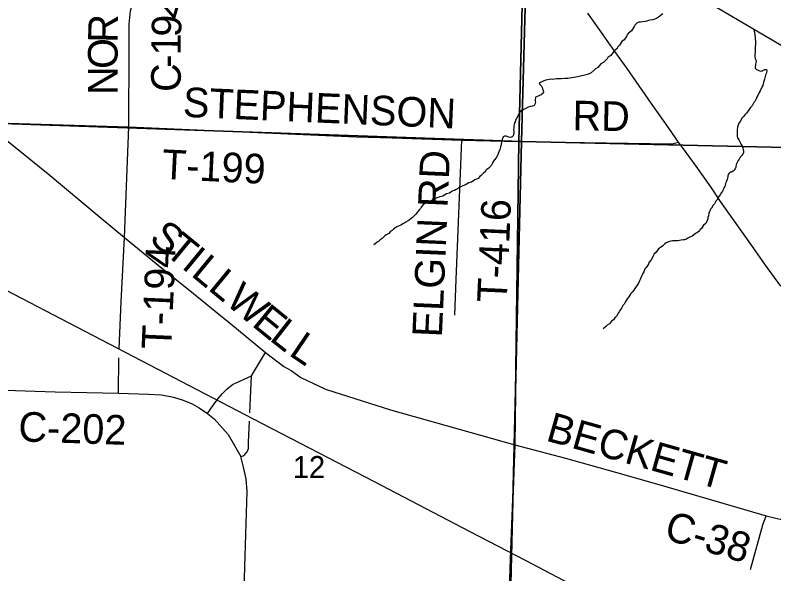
# Model space of a CAD drawing. Extents: x 0 to 34, y 0 to 22.
# Drawn here: x 4.391 to 5.846, y 15.693 to 16.765 of the extents above; entities that cross this region are included whole.
import ezdxf

# ---------------------------------------------------------------- set-up
doc = ezdxf.new("R2010")
doc.units = 0
for name, color, linetype in [('Default', 7, 'Continuous'), ('GM_X_County_Road', 7, 'Continuous'), ('GM_X_County_Road_Text', 7, 'Continuous'), ('GM_X_Minor_River', 7, 'Continuous'), ('GM_X_Rail_Line', 7, 'Continuous'), ('GM_X_Section', 7, 'Continuous'), ('GM_X_Section_Text', 7, 'Continuous'), ('GM_X_Township_Road', 7, 'Continuous'), ('GM_X_Township_Road_Text', 7, 'Continuous'), ('GM_X_US_Route', 7, 'Continuous'), ('SH_Text', 7, 'Continuous')]:
    doc.layers.add(name, color=color, linetype=linetype)

msp = doc.modelspace()

# ---------------------------------------------------------------- linework, layer by layer
at = {"layer": 'Default'}
for points in [[(5.3679, 16.9967), (5.3666, 16.941), (5.3568, 16.5234), (5.3489, 15.9414), (5.3456, 15.8536), (5.3407, 15.722), (5.3386, 15.6646)], [(5.3386, 15.6646), (5.3407, 15.722), (5.3456, 15.8536), (5.3489, 15.9414), (5.3568, 16.5234), (5.3666, 16.941), (5.3679, 16.9967)]]:
    msp.add_lwpolyline(points, dxfattribs=at)
at = {"layer": 'GM_X_County_Road'}
for points in [[(4.6008, 16.339), (4.609, 16.551), (4.6097, 16.6991), (4.6094, 16.7478), (4.6122, 16.7735), (4.6186, 16.7955), (4.6308, 16.8329), (4.6404, 16.8545), (4.6484, 16.8669), (4.6536, 16.8737), (4.6626, 16.8795), (4.6788, 16.8827), (4.6826, 16.8976), (4.6855, 16.9599), (4.6881, 17.0461), (4.7038, 17.5502)], [(2.8366, 17.427), (2.8842, 17.4004), (2.9456, 17.3674), (3.0402, 17.3171), (3.14, 17.2646), (3.2189, 17.2229), (3.3942, 17.1285), (3.5659, 17.0329), (3.7657, 16.9226), (3.8318, 16.8854), (3.9996, 16.7931), (4.1007, 16.7381), (4.138, 16.7114), (4.1787, 16.6782), (4.3308, 16.5597), (4.3911, 16.5119), (4.4541, 16.461), (4.552, 16.3788), (4.6008, 16.339), (4.6722, 16.2801), (4.7258, 16.2367), (4.7883, 16.1861)], [(4.7883, 16.1861), (4.8004, 16.1763), (4.8711, 16.1183), (4.9063, 16.0915), (4.9201, 16.0832), (4.9384, 16.0698), (4.9847, 16.0482)], [(4.7598, 16.001), (4.7713, 16.0175), (4.7803, 16.0295), (4.7887, 16.0392), (4.7964, 16.0478), (4.8077, 16.0567), (4.844, 16.0731), (4.8711, 16.1183)], [(4.3333, 16.047), (4.4673, 16.0429), (4.5889, 16.0401)], [(4.9847, 16.0482), (4.9875, 16.0469), (5.1107, 16.0081), (5.3492, 15.9409)], [(4.5889, 16.0401), (4.6466, 16.0383), (4.6717, 16.0367), (4.6942, 16.0323), (4.7129, 16.0263), (4.7301, 16.0196), (4.7434, 16.012), (4.7598, 16.001)], [(5.3492, 15.9409), (5.4463, 15.9156), (5.558, 15.8841), (5.6405, 15.8603), (5.7937, 15.8156), (5.8306, 15.8045), (5.9105, 15.7856), (5.9646, 15.7778), (6.0771, 15.7639), (6.1234, 15.7574)]]:
    msp.add_lwpolyline(points, dxfattribs=at)
at = {"layer": 'GM_X_Minor_River'}
for points in [[(5.6328, 16.7675), (5.6247, 16.7612), (5.6208, 16.7591), (5.6135, 16.7566), (5.6086, 16.7556), (5.6055, 16.7549), (5.6021, 16.7538), (5.599, 16.7528), (5.5944, 16.7525), (5.5899, 16.7519), (5.5868, 16.7516), (5.583, 16.7501), (5.5787, 16.7461), (5.5779, 16.7438), (5.5724, 16.7352), (5.5666, 16.7308), (5.5638, 16.7271), (5.563, 16.7244), (5.5583, 16.7181), (5.5544, 16.7147), (5.5497, 16.7076), (5.5458, 16.7039), (5.545, 16.7013), (5.5411, 16.698), (5.5387, 16.6958), (5.5328, 16.6876), (5.5271, 16.6839), (5.5262, 16.6816), (5.5196, 16.675), (5.5138, 16.6717), (5.508, 16.665), (5.5037, 16.6624), (5.501, 16.6599), (5.4952, 16.6547), (5.4929, 16.6532), (5.4883, 16.6514), (5.4833, 16.6504), (5.4749, 16.6483), (5.4661, 16.6463), (5.4585, 16.6453), (5.4505, 16.644), (5.4447, 16.6438), (5.4383, 16.6432), (5.4333, 16.6433), (5.4288, 16.643), (5.4249, 16.6424), (5.4211, 16.6421), (5.4181, 16.6422), (5.4146, 16.6415), (5.4082, 16.6405), (5.4047, 16.6391), (5.3997, 16.6365), (5.3959, 16.6355), (5.3969, 16.6324), (5.3999, 16.6289), (5.4014, 16.6266)], [(5.8074, 16.738), (5.8088, 16.7283), (5.8104, 16.7138), (5.8093, 16.6849)], [(5.8093, 16.6849), (5.81, 16.6818), (5.811, 16.6795), (5.8114, 16.6765), (5.8105, 16.6712), (5.8104, 16.6685), (5.81, 16.6659), (5.8099, 16.6636), (5.8125, 16.6609), (5.8167, 16.6589), (5.8197, 16.6576), (5.8231, 16.6587), (5.8254, 16.6598), (5.8281, 16.6608), (5.8312, 16.6612), (5.8318, 16.6577), (5.8306, 16.6528), (5.8298, 16.6502), (5.8277, 16.6422), (5.8265, 16.6389), (5.826, 16.6366), (5.8244, 16.6306), (5.8224, 16.6272), (5.8196, 16.62), (5.8172, 16.6167), (5.8144, 16.6099), (5.812, 16.6069), (5.8116, 16.6047), (5.8088, 16.5998), (5.8069, 16.5976), (5.8057, 16.5949), (5.8037, 16.5912), (5.8009, 16.5882), (5.7962, 16.5819), (5.7939, 16.5777), (5.7904, 16.5748), (5.7876, 16.5707), (5.7845, 16.5681), (5.7809, 16.561), (5.7786, 16.558), (5.7757, 16.5501), (5.7752, 16.5452), (5.7755, 16.5425), (5.7754, 16.5383), (5.775, 16.5353), (5.7753, 16.533), (5.776, 16.5299), (5.7786, 16.5261), (5.7815, 16.5199), (5.7829, 16.5172), (5.7848, 16.5145), (5.7862, 16.5099), (5.7869, 16.5073), (5.7876, 16.5042), (5.7875, 16.5015), (5.7863, 16.4985), (5.784, 16.4959), (5.7812, 16.493), (5.7792, 16.4888), (5.7773, 16.4862), (5.7749, 16.4813), (5.7733, 16.4787), (5.7724, 16.4734), (5.7716, 16.4704), (5.7696, 16.4678), (5.7673, 16.466), (5.7642, 16.4641), (5.7619, 16.4638), (5.7596, 16.462), (5.758, 16.4597), (5.7564, 16.4526), (5.7559, 16.4499), (5.7547, 16.4465), (5.7535, 16.4443), (5.7514, 16.4367), (5.7495, 16.4337), (5.749, 16.4315), (5.747, 16.4273), (5.7451, 16.4251), (5.7427, 16.4206), (5.74, 16.4176), (5.736, 16.4105), (5.7344, 16.4083), (5.732, 16.403), (5.7293, 16.4008), (5.7261, 16.3952), (5.7242, 16.393), (5.7222, 16.3881), (5.721, 16.3858), (5.7201, 16.3801), (5.7192, 16.3771), (5.7188, 16.3745), (5.718, 16.3715), (5.7152, 16.3658), (5.7109, 16.3621), (5.707, 16.3562), (5.7043, 16.3543), (5.7027, 16.3517), (5.6992, 16.348), (5.6953, 16.3466), (5.6918, 16.3429)], [(5.4014, 16.6266), (5.4021, 16.6239), (5.4035, 16.6205), (5.4038, 16.6178), (5.403, 16.6156), (5.3991, 16.6126), (5.3964, 16.6112), (5.3938, 16.6101), (5.3915, 16.609), (5.3888, 16.6076), (5.3879, 16.6027), (5.3878, 16.5996), (5.3885, 16.5973), (5.3873, 16.5943), (5.3857, 16.5921), (5.3827, 16.5906), (5.3792, 16.5899), (5.3742, 16.5886), (5.3677, 16.5849), (5.3635, 16.5835), (5.3596, 16.5813), (5.358, 16.5787), (5.3557, 16.5738), (5.3513, 16.566), (5.3501, 16.5637), (5.3493, 16.5607), (5.3484, 16.5584), (5.3476, 16.5554), (5.3472, 16.5531), (5.3467, 16.5482), (5.3466, 16.5459), (5.347, 16.5436), (5.3469, 16.5391), (5.3464, 16.5368), (5.3456, 16.5338), (5.344, 16.5316), (5.3398, 16.5305), (5.3372, 16.5314), (5.3326, 16.533), (5.3288, 16.5331), (5.3265, 16.532), (5.3245, 16.5264), (5.3241, 16.5237), (5.3232, 16.5211), (5.3223, 16.5146), (5.3215, 16.5124), (5.3203, 16.5078), (5.3183, 16.5033), (5.3167, 16.4996), (5.3162, 16.4973), (5.3134, 16.4913), (5.3095, 16.4872), (5.3068, 16.4835), (5.3056, 16.4801), (5.304, 16.4775), (5.2993, 16.4719), (5.2935, 16.4679), (5.2927, 16.4652), (5.2888, 16.4623), (5.2845, 16.4578), (5.2818, 16.4556), (5.2787, 16.4519), (5.2725, 16.4494), (5.2656, 16.4446), (5.2606, 16.4436), (5.2544, 16.4396), (5.2494, 16.4378), (5.2429, 16.4349), (5.239, 16.432), (5.2367, 16.4305), (5.2333, 16.4291), (5.229, 16.4273), (5.2236, 16.424), (5.2179, 16.4223), (5.2106, 16.4183), (5.2048, 16.4169), (5.201, 16.4155), (5.1964, 16.4133), (5.1933, 16.4122), (5.1891, 16.4089), (5.1841, 16.4075), (5.1775, 16.4039), (5.1737, 16.4025), (5.1718, 16.4002), (5.1694, 16.3969), (5.1682, 16.3942), (5.1659, 16.3924), (5.1635, 16.389), (5.1615, 16.3864), (5.1588, 16.3835), (5.1553, 16.3794), (5.1526, 16.3772), (5.1502, 16.3749), (5.1464, 16.372), (5.1441, 16.3709), (5.1402, 16.368), (5.1379, 16.3669), (5.1356, 16.3654), (5.1302, 16.3625), (5.1271, 16.3611), (5.1229, 16.3589)], [(5.1229, 16.3589), (5.1186, 16.3564), (5.1163, 16.3545), (5.1136, 16.3519), (5.1101, 16.3493), (5.1074, 16.3464), (5.1047, 16.3453), (5.1024, 16.3438), (5.0997, 16.3416), (5.0966, 16.339), (5.0946, 16.3368), (5.0907, 16.3339), (5.0872, 16.3313), (5.0849, 16.3298), (5.0811, 16.3265), (5.0783, 16.3243)], [(5.6918, 16.3429), (5.6887, 16.3414), (5.6857, 16.34), (5.683, 16.3385), (5.6807, 16.3371), (5.6783, 16.3352), (5.6745, 16.3342), (5.6715, 16.3339), (5.6677, 16.3336), (5.6612, 16.3322), (5.657, 16.3323), (5.6543, 16.332), (5.6513, 16.3321), (5.6478, 16.3318), (5.6436, 16.3304), (5.639, 16.3282), (5.6363, 16.3264), (5.6328, 16.3227), (5.6285, 16.3197), (5.6243, 16.3172), (5.6192, 16.3101), (5.6153, 16.3068), (5.6145, 16.3041), (5.6101, 16.2959), (5.6058, 16.291), (5.605, 16.2876), (5.6006, 16.2809), (5.5983, 16.2783), (5.5963, 16.2727), (5.5943, 16.2693), (5.5927, 16.2655), (5.5907, 16.261), (5.5895, 16.2584), (5.5879, 16.2558), (5.5859, 16.2513), (5.5819, 16.2453), (5.5788, 16.2408), (5.5768, 16.2374), (5.5741, 16.2337), (5.5713, 16.2311), (5.5674, 16.2248), (5.5646, 16.221), (5.5627, 16.2177), (5.5607, 16.2147), (5.5583, 16.2109), (5.556, 16.2083), (5.5536, 16.2034), (5.5516, 16.2008), (5.5492, 16.196), (5.5469, 16.1934), (5.5437, 16.1874), (5.5406, 16.1848), (5.5379, 16.181), (5.534, 16.1781), (5.5304, 16.1729), (5.5262, 16.1703), (5.5227, 16.167), (5.5181, 16.1633)]]:
    msp.add_lwpolyline(points, dxfattribs=at)
at = {"layer": 'GM_X_Rail_Line'}
msp.add_lwpolyline([(4.034, 16.414), (4.8469, 15.9911), (5.0791, 15.8704), (5.2629, 15.7745), (5.3698, 15.7189), (5.5376, 15.6307)], dxfattribs=at)
at = {"layer": 'GM_X_Section'}
for points in [[(4.38, 17.558), (5.3894, 17.5316), (5.3619, 16.5226), (4.3467, 16.5583)], [(5.3894, 17.5316), (6.392, 17.5084), (6.4295, 17.5071), (6.4046, 16.4989), (5.3619, 16.5226)], [(4.3467, 16.5583), (5.3619, 16.5226), (5.3374, 15.5147), (4.3136, 15.5403)], [(5.3619, 16.5226), (6.4046, 16.4989), (6.384, 15.4928), (5.3374, 15.5147)]]:
    msp.add_lwpolyline(points, close=True, dxfattribs=at)
at = {"layer": 'GM_X_Township_Road'}
for p, q in [((4.3308, 16.5597), (4.609, 16.551)), ((4.5889, 16.0401), (4.5894, 16.1079)), ((4.841, 16.0022), (4.844, 16.0731))]:
    msp.add_line(p, q, dxfattribs=at)
for points in [[(4.609, 16.551), (5.0447, 16.5316), (5.1136, 16.5297), (5.2466, 16.5253), (5.3561, 16.5229)], [(5.2466, 16.5253), (5.2359, 16.2578), (5.233, 16.1895)], [(5.3561, 16.5229), (5.3571, 16.5229), (5.6497, 16.5184), (5.6629, 16.5215)], [(4.5903, 16.1252), (4.5938, 16.2154), (4.6008, 16.339)], [(4.7598, 16.001), (4.7725, 15.9906), (4.7993, 15.9609), (4.8233, 15.9183)], [(4.8333, 15.7696), (4.8359, 15.8515), (4.8338, 15.8756), (4.8289, 15.8979), (4.8233, 15.9183), (4.8279, 15.92), (4.8314, 15.9225), (4.8356, 15.9272), (4.8381, 15.9336), (4.8383, 15.9462), (4.84, 15.9863)], [(5.3075, 14.5097), (5.3164, 14.8543), (5.3332, 15.5092), (5.3336, 15.5268), (5.3363, 15.5972), (5.3388, 15.6641), (5.3409, 15.7215), (5.3459, 15.8531), (5.3492, 15.9409)], [(5.8006, 15.7019), (5.8246, 15.7871), (5.8306, 15.8045)], [(4.8022, 14.5214), (4.805, 14.64), (4.8097, 14.8671), (4.8126, 15.1889), (4.8254, 15.5169), (4.8333, 15.7696)]]:
    msp.add_lwpolyline(points, dxfattribs=at)
at = {"layer": 'GM_X_US_Route'}
msp.add_lwpolyline([(5.8588, 16.2451), (5.8298, 16.2857), (5.8014, 16.3262), (5.7704, 16.37), (5.7433, 16.408), (5.7245, 16.4358), (5.6967, 16.4754), (5.6723, 16.5091), (5.6629, 16.5215), (5.6387, 16.557), (5.6104, 16.5967), (5.5874, 16.6294), (5.5642, 16.6627), (5.5409, 16.6953), (5.5186, 16.7276), (5.4892, 16.7689)], dxfattribs=at)
at = {"layer": 'SH_Text'}
msp.add_lwpolyline([(6.0096, 16.9213), (7.8264, 16.9213), (7.8264, 16.5183), (6.0096, 16.5183), (6.0096, 16.619), (5.3006, 17.0363), (6.0096, 16.7198)], close=True, dxfattribs=at)

# ---------------------------------------------------------------- texts
at = {"layer": 'GM_X_County_Road_Text'}
for s, height, rotation, p in [('4', 0.0568, 73.4817, (4.7097, 16.7537)), ('R', 0.0568, 88.9041, (4.5873, 16.7119)), ('9', 0.0568, 86.945, (4.7085, 16.7222)), ('O', 0.0568, 89.9781, (4.5873, 16.6621)), ('1', 0.0568, 89.8543, (4.7084, 16.6879)), ('-', 0.0568, 89.9727, (4.7084, 16.6646)), ('N', 0.0568, 90, (4.5873, 16.6122)), ('C', 0.0568, 89.9971, (4.7084, 16.618)), ('S', 0.0568, 320.5499, (4.6455, 16.3328)), ('T', 0.0568, 320.5451, (4.6751, 16.3084)), ('I', 0.0568, 320.5517, (4.708, 16.2814)), ('L', 0.0568, 320.549, (4.726, 16.2666)), ('L', 0.0568, 320.5451, (4.7588, 16.2396)), ('W', 0.0568, 320.552, (4.7916, 16.2125)), ('E', 0.0568, 320.6867, (4.8426, 16.1706)), ('L', 0.0568, 321.9785, (4.8765, 16.1428)), ('L', 0.0568, 325.9284, (4.9135, 16.1141)), ('C-202', 0.05682, 358.0725, (4.3964, 15.9477)), ('BECKETT', 0.05682, 344.238, (5.4065, 15.9495)), ('C-38', 0.05682, 343.2015, (5.6328, 15.761))]:
    msp.add_text(s, height=height, rotation=rotation, dxfattribs=at).set_placement(p)
at = {"layer": 'GM_X_Section_Text'}
msp.add_text('12', height=0.04186, rotation=0, dxfattribs=at).set_placement((4.923, 15.8775))
at = {"layer": 'GM_X_Township_Road_Text'}
for s, rotation, p in [('STEPHENSON', 357.5413, (4.7117, 16.5703)), ('RD', 359.0128, (5.4592, 16.5445)), ('T-199', 357.1941, (4.6715, 16.4512)), ('ELGIN RD', 87.4846, (5.209, 16.1465)), ('T-416', 87.4736, (5.3332, 16.2131)), ('T-194', 87.4868, (4.6899, 16.1233))]:
    msp.add_text(s, height=0.05682, rotation=rotation, dxfattribs=at).set_placement(p)

doc.saveas('drawing.dxf')
